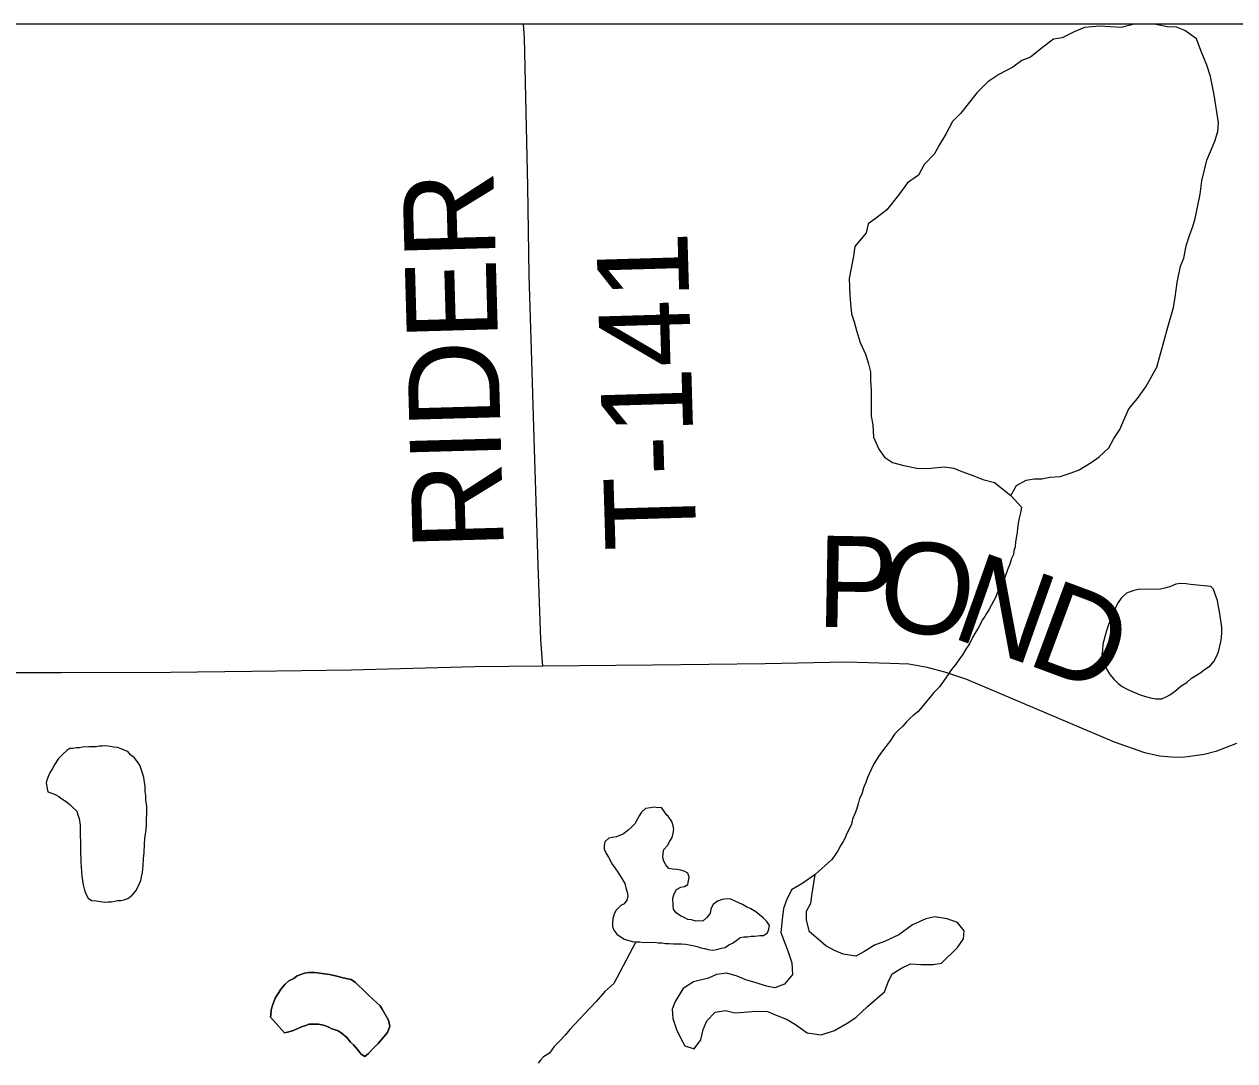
# Model space of a CAD drawing. Extents: x 10.6 to 44.6, y -2.6 to 23.4.
# Drawn here: x 15.419 to 16.174, y 21.68 to 22.327 of the extents above; entities that cross this region are included whole.
import ezdxf

# ---------------------------------------------------------------- set-up
doc = ezdxf.new("R2010")
doc.units = 0
for name, color, linetype in [('GM_X_County', 7, 'Continuous'), ('GM_X_Minor_Lake', 7, 'Continuous'), ('GM_X_Minor_River', 7, 'Continuous'), ('GM_X_Township', 7, 'Continuous'), ('GM_X_Township_Road', 7, 'Continuous'), ('GM_X_Township_Road_Text', 7, 'Continuous')]:
    doc.layers.add(name, color=color, linetype=linetype)

msp = doc.modelspace()

# ---------------------------------------------------------------- linework, layer by layer
at = {"layer": 'GM_X_County'}
msp.add_lwpolyline([(20.00331, 15.53022), (20.00331, 22.32669), (13.20331, 22.32669), (13.20331, 15.52669), (19.84134, 15.52669)], dxfattribs=at)
at = {"layer": 'GM_X_Minor_Lake'}
for points in [[(16.11082, 22.32669), (16.10952, 22.32625), (16.10307, 22.32473), (16.09624, 22.3251), (16.08979, 22.32547), (16.08031, 22.3247), (16.07386, 22.32204), (16.06627, 22.31823), (16.06096, 22.31746), (16.05413, 22.31214), (16.04654, 22.30605), (16.04123, 22.30415), (16.03553, 22.29996), (16.02681, 22.2954), (16.01998, 22.29083), (16.01315, 22.28399), (16.00935, 22.27905), (16.0029, 22.27106), (15.99797, 22.26612), (15.99379, 22.25814), (15.98962, 22.2513), (15.98658, 22.24598), (15.98013, 22.23913), (15.97672, 22.23267), (15.96988, 22.22772), (15.96419, 22.22012), (15.95698, 22.211), (15.95053, 22.20605), (15.94522, 22.20225), (15.94408, 22.19655), (15.93687, 22.18819), (15.93611, 22.18211), (15.93345, 22.16805), (15.93383, 22.1578), (15.93421, 22.15248), (15.93497, 22.14602), (15.93649, 22.14109), (15.938, 22.13577), (15.94028, 22.12818), (15.94369, 22.12097), (15.94559, 22.11489), (15.94672, 22.10995), (15.94672, 22.10464), (15.9471, 22.09856), (15.9471, 22.08223), (15.94824, 22.07691), (15.94862, 22.06932), (15.95203, 22.06172), (15.95544, 22.05679), (15.96038, 22.05338), (15.96758, 22.05149), (15.97555, 22.04998), (15.98238, 22.0496), (15.99263, 22.05076), (15.9987, 22.05), (16.00363, 22.04773), (16.01122, 22.04508), (16.01691, 22.04281), (16.02412, 22.04092), (16.03436, 22.03295)], [(16.05371, 22.04323), (16.05864, 22.04437), (16.06509, 22.04476), (16.07192, 22.04705), (16.07685, 22.04895), (16.08444, 22.05352), (16.08938, 22.05694), (16.09545, 22.06264), (16.09848, 22.06834), (16.10228, 22.07405), (16.10531, 22.08127), (16.10797, 22.08697), (16.11328, 22.09343), (16.1186, 22.10065), (16.12543, 22.11281), (16.13226, 22.13789), (16.13568, 22.15005), (16.13682, 22.1565), (16.13796, 22.16562), (16.14023, 22.17588), (16.14213, 22.18082), (16.14365, 22.18842), (16.14593, 22.19564), (16.14783, 22.20058), (16.14934, 22.20552), (16.15238, 22.22071), (16.15352, 22.22907), (16.15656, 22.24199), (16.15884, 22.24731), (16.16149, 22.25377), (16.16339, 22.25984), (16.16377, 22.26516), (16.16112, 22.28263), (16.15884, 22.29402), (16.15656, 22.30124), (16.15277, 22.31035), (16.15012, 22.31756), (16.14291, 22.32287), (16.1376, 22.32477), (16.13191, 22.32514), (16.12584, 22.32627), (16.12351, 22.32669)], [(16.03436, 22.03295), (16.03777, 22.03903), (16.04384, 22.04246), (16.04878, 22.04322), (16.05371, 22.04323)], [(16.15912, 21.9761), (16.14629, 21.97736), (16.14363, 21.9777), (16.14021, 21.97803), (16.13718, 21.97761), (16.13379, 21.97605), (16.13114, 21.97526), (16.12773, 21.97445), (16.11369, 21.97427), (16.11029, 21.97346), (16.10652, 21.97189), (16.10314, 21.96881), (16.10127, 21.96613), (16.09979, 21.96345), (16.09869, 21.96002), (16.09647, 21.95582), (16.095, 21.95162), (16.0939, 21.94857), (16.09318, 21.94553), (16.09173, 21.94019), (16.09139, 21.93639), (16.09105, 21.93373), (16.09185, 21.93032), (16.09264, 21.92768), (16.0942, 21.92428), (16.09613, 21.92127), (16.09845, 21.91826), (16.10114, 21.91564), (16.10382, 21.91378), (16.10649, 21.9123), (16.10955, 21.91082), (16.11488, 21.90861), (16.11831, 21.90752), (16.12136, 21.9068), (16.12478, 21.90609), (16.12858, 21.90614)], [(16.12858, 21.90614), (16.13122, 21.90731), (16.13386, 21.90886), (16.13724, 21.91118), (16.14062, 21.91426), (16.14401, 21.91621), (16.14701, 21.91891), (16.15229, 21.92201), (16.15567, 21.92471), (16.15868, 21.92665), (16.16093, 21.92934), (16.16241, 21.93202), (16.16389, 21.93545), (16.16533, 21.94154), (16.16568, 21.94421), (16.16601, 21.94763), (16.16598, 21.95066), (16.16556, 21.95369), (16.16432, 21.96165), (16.16353, 21.96468), (16.16311, 21.96733), (16.16193, 21.97073), (16.16075, 21.97451), (16.15912, 21.9761)], [(15.49327, 21.80654), (15.49357, 21.81035), (15.49384, 21.81529), (15.49414, 21.8191), (15.49447, 21.82177), (15.49479, 21.82444), (15.4951, 21.82748), (15.49502, 21.83128), (15.49534, 21.83433), (15.49524, 21.83888), (15.49477, 21.84305), (15.49471, 21.84571), (15.49428, 21.84836), (15.49421, 21.8514), (15.49377, 21.85405), (15.49333, 21.85708), (15.49251, 21.85972), (15.49088, 21.86463), (15.48892, 21.86762), (15.48736, 21.86949), (15.48542, 21.87097), (15.48348, 21.8732), (15.48156, 21.87392), (15.47925, 21.87501), (15.47695, 21.87572), (15.47466, 21.87605), (15.47238, 21.87638), (15.4697, 21.8767), (15.46742, 21.87666), (15.46552, 21.87662), (15.46363, 21.87619), (15.46097, 21.87614), (15.45907, 21.87609), (15.45526, 21.87601), (15.45337, 21.87559), (15.45147, 21.87555), (15.4492, 21.87512), (15.4473, 21.87508), (15.44542, 21.8739), (15.44281, 21.87156), (15.4402, 21.86884), (15.43799, 21.86538), (15.43653, 21.86268), (15.43506, 21.86037), (15.43397, 21.85807), (15.43288, 21.85538), (15.43254, 21.85348), (15.43365, 21.84813)], [(15.43365, 21.84813), (15.43533, 21.84746), (15.43802, 21.84638), (15.44033, 21.84529), (15.44226, 21.84381), (15.44496, 21.84197), (15.44728, 21.84012), (15.44923, 21.83826), (15.45156, 21.83603), (15.45236, 21.83377), (15.45317, 21.83151), (15.45364, 21.82734), (15.45369, 21.82506), (15.45374, 21.82278), (15.4538, 21.82012), (15.45384, 21.81784), (15.4539, 21.81519), (15.45396, 21.81253), (15.45402, 21.80987), (15.45408, 21.80683), (15.45414, 21.80417), (15.45471, 21.79545), (15.45514, 21.79279), (15.45558, 21.79014), (15.45641, 21.78674), (15.45722, 21.78448), (15.4588, 21.78185), (15.46074, 21.78038), (15.46378, 21.78006), (15.46645, 21.77974), (15.46874, 21.77941), (15.47102, 21.77946), (15.47331, 21.77951), (15.4752, 21.77993), (15.47709, 21.78035), (15.47899, 21.78039), (15.48089, 21.78081), (15.48353, 21.78163), (15.48615, 21.78359), (15.48838, 21.7863), (15.48948, 21.78822), (15.49057, 21.79052), (15.49166, 21.79283), (15.49199, 21.79512), (15.4927, 21.79779), (15.49299, 21.80198), (15.49327, 21.80654), (15.49357, 21.81035), (15.49384, 21.81529), (15.49414, 21.8191), (15.49447, 21.82177), (15.49479, 21.82444), (15.4951, 21.82748), (15.49502, 21.83128), (15.49534, 21.83433), (15.49524, 21.83888), (15.49477, 21.84305), (15.49471, 21.84571), (15.49428, 21.84836), (15.49421, 21.8514), (15.49377, 21.85405), (15.49333, 21.85708), (15.49251, 21.85972), (15.49088, 21.86463), (15.48892, 21.86762), (15.48736, 21.86949), (15.48542, 21.87097), (15.48348, 21.8732), (15.48156, 21.87392), (15.47925, 21.87501), (15.47695, 21.87572), (15.47466, 21.87605), (15.47238, 21.87638), (15.4697, 21.8767), (15.46742, 21.87666), (15.46552, 21.87662), (15.46363, 21.87619), (15.46097, 21.87614), (15.45907, 21.87609), (15.45526, 21.87601), (15.45337, 21.87559), (15.45147, 21.87555), (15.4492, 21.87512), (15.4473, 21.87508), (15.44542, 21.8739), (15.44281, 21.87156), (15.4402, 21.86884), (15.43799, 21.86538), (15.43653, 21.86268), (15.43506, 21.86037), (15.43397, 21.85807), (15.43288, 21.85538), (15.43254, 21.85348), (15.43365, 21.84813)], [(15.43365, 21.84813), (15.43533, 21.84746), (15.43802, 21.84638), (15.44033, 21.84529), (15.44226, 21.84381), (15.44496, 21.84197), (15.44728, 21.84012), (15.44923, 21.83826), (15.45156, 21.83603), (15.45236, 21.83377), (15.45317, 21.83151), (15.45364, 21.82734), (15.45369, 21.82506), (15.45374, 21.82278), (15.4538, 21.82012), (15.45384, 21.81784), (15.4539, 21.81519), (15.45396, 21.81253), (15.45402, 21.80987), (15.45408, 21.80683), (15.45414, 21.80417), (15.45471, 21.79545), (15.45514, 21.79279), (15.45558, 21.79014), (15.45641, 21.78674), (15.45722, 21.78448), (15.4588, 21.78185), (15.46074, 21.78038), (15.46378, 21.78006), (15.46645, 21.77974), (15.46874, 21.77941), (15.47102, 21.77946), (15.47331, 21.77951), (15.4752, 21.77993), (15.47709, 21.78035), (15.47899, 21.78039), (15.48089, 21.78081), (15.48353, 21.78163), (15.48615, 21.78359), (15.48838, 21.7863), (15.48948, 21.78822), (15.49057, 21.79052), (15.49166, 21.79283), (15.49199, 21.79512), (15.4927, 21.79779), (15.49299, 21.80198), (15.49327, 21.80654)], [(15.81979, 21.83352), (15.81634, 21.83823), (15.81406, 21.8382), (15.81178, 21.83855), (15.80951, 21.83814), (15.80648, 21.83772), (15.80385, 21.83541), (15.80236, 21.83311), (15.80125, 21.83082), (15.79977, 21.82814), (15.79752, 21.82584), (15.79526, 21.82391), (15.79263, 21.82197), (15.79037, 21.82081), (15.7881, 21.82002), (15.78583, 21.81961), (15.78356, 21.8192), (15.78093, 21.81688), (15.78058, 21.8146), (15.78061, 21.81232), (15.78178, 21.80968), (15.78332, 21.80743), (15.78566, 21.8029), (15.7872, 21.80064), (15.78913, 21.79801), (15.79068, 21.79576), (15.79223, 21.79312), (15.79339, 21.79086), (15.79419, 21.78821), (15.79498, 21.78556), (15.79538, 21.78329), (15.79466, 21.78062), (15.79317, 21.77833), (15.79091, 21.77716), (15.78791, 21.77408), (15.7868, 21.77179), (15.78607, 21.76912), (15.78573, 21.76646)], [(15.88257, 21.76015), (15.8833, 21.76244), (15.88366, 21.76472), (15.8821, 21.76735), (15.8798, 21.7696), (15.8752, 21.77334), (15.87214, 21.7752), (15.86947, 21.7763), (15.8668, 21.77778), (15.86451, 21.77889), (15.86222, 21.78), (15.85955, 21.7811), (15.85727, 21.78145), (15.85423, 21.78103), (15.85121, 21.77985), (15.84858, 21.77792), (15.84709, 21.77524), (15.84675, 21.7722), (15.84451, 21.76952), (15.84226, 21.76759), (15.8377, 21.76753), (15.83504, 21.76825), (15.83276, 21.7686), (15.83046, 21.76971), (15.82817, 21.77082), (15.8255, 21.77268), (15.82395, 21.77494), (15.82354, 21.77721), (15.82349, 21.78177), (15.82421, 21.78443), (15.8257, 21.78711), (15.82833, 21.78866), (15.83061, 21.78907), (15.83287, 21.79024), (15.83357, 21.7948), (15.83278, 21.79745), (15.83049, 21.79856), (15.8282, 21.79929), (15.82592, 21.79964), (15.82326, 21.79998), (15.82098, 21.80033), (15.81905, 21.80258), (15.81789, 21.80485), (15.8171, 21.80711), (15.81745, 21.80978), (15.8178, 21.81206), (15.82004, 21.81474), (15.82153, 21.81742), (15.82302, 21.81972), (15.82374, 21.82238), (15.82409, 21.82467), (15.82369, 21.82694), (15.8229, 21.82959), (15.82058, 21.83297), (15.81979, 21.83352)], [(15.91216, 21.79657), (15.90457, 21.79124), (15.89736, 21.78706), (15.89432, 21.7806), (15.89242, 21.77528), (15.89166, 21.76844), (15.8909, 21.76046), (15.89545, 21.74831), (15.89773, 21.74148), (15.89811, 21.73426), (15.89317, 21.72818), (15.8871, 21.7259), (15.88179, 21.72703), (15.87534, 21.72892), (15.86889, 21.73081), (15.86358, 21.73309), (15.85713, 21.73498), (15.85068, 21.73421), (15.84575, 21.73193), (15.83626, 21.72964), (15.82981, 21.72545), (15.82488, 21.71747), (15.82298, 21.71253), (15.82336, 21.70683), (15.82563, 21.7), (15.82829, 21.69468), (15.83095, 21.68975), (15.83664, 21.68786), (15.84081, 21.69356), (15.84233, 21.70002), (15.84461, 21.70534), (15.84992, 21.71066), (15.85637, 21.71181), (15.86206, 21.7103), (15.86775, 21.71068), (15.87534, 21.71145), (15.88255, 21.71108), (15.889, 21.70843), (15.89469, 21.70616)], [(15.91216, 21.79657), (15.90457, 21.79124), (15.89736, 21.78706), (15.89432, 21.7806), (15.89242, 21.77528), (15.89166, 21.76844), (15.8909, 21.76046), (15.89545, 21.74831), (15.89773, 21.74148), (15.89811, 21.73426), (15.89317, 21.72818), (15.8871, 21.7259), (15.88179, 21.72703), (15.87534, 21.72892), (15.86889, 21.73081), (15.86358, 21.73309), (15.85713, 21.73498), (15.85068, 21.73421), (15.84575, 21.73193), (15.83626, 21.72964), (15.82981, 21.72545), (15.82488, 21.71747), (15.82298, 21.71253), (15.82336, 21.70683), (15.82563, 21.7), (15.82829, 21.69468), (15.83095, 21.68975), (15.83664, 21.68786), (15.84081, 21.69356), (15.84233, 21.70002), (15.84461, 21.70534), (15.84992, 21.71066), (15.85637, 21.71181), (15.86206, 21.7103), (15.86775, 21.71068), (15.87534, 21.71145), (15.88255, 21.71108), (15.889, 21.70843), (15.89469, 21.70616), (15.9, 21.70312), (15.90721, 21.69781), (15.91594, 21.69668), (15.92428, 21.69935), (15.93225, 21.70392), (15.93756, 21.70734), (15.94477, 21.71419), (15.9554, 21.72331), (15.95768, 21.72939), (15.96033, 21.73472), (15.96602, 21.73814), (15.97172, 21.74081), (15.97817, 21.74043), (15.98575, 21.74044), (15.99107, 21.74121), (16.00093, 21.75109), (16.00473, 21.75641), (16.00511, 21.76135), (16.00093, 21.76667), (15.99448, 21.76894), (15.9869, 21.77007), (15.9812, 21.76892), (15.97286, 21.76512), (15.96451, 21.75903), (15.9554, 21.75484), (15.94933, 21.75256), (15.9425, 21.74837), (15.93757, 21.7457), (15.9296, 21.74683), (15.92429, 21.74911), (15.91898, 21.75214), (15.91405, 21.75631), (15.90874, 21.76086), (15.90684, 21.76808), (15.90684, 21.77378), (15.9095, 21.77872), (15.91026, 21.78479), (15.91216, 21.79657)], [(15.89469, 21.70616), (15.9, 21.70312), (15.90721, 21.69781), (15.91594, 21.69668), (15.92428, 21.69935), (15.93225, 21.70392), (15.93756, 21.70734), (15.94477, 21.71419), (15.9554, 21.72331), (15.95768, 21.72939), (15.96033, 21.73472), (15.96602, 21.73814), (15.97172, 21.74081), (15.97817, 21.74043), (15.98575, 21.74044), (15.99107, 21.74121), (16.00093, 21.75109), (16.00473, 21.75641), (16.00511, 21.76135), (16.00093, 21.76667), (15.99448, 21.76894), (15.9869, 21.77007), (15.9812, 21.76892), (15.97286, 21.76512), (15.96451, 21.75903), (15.9554, 21.75484), (15.94933, 21.75256), (15.9425, 21.74837), (15.93757, 21.7457), (15.9296, 21.74683), (15.92429, 21.74911), (15.91898, 21.75214), (15.91405, 21.75631), (15.90874, 21.76086), (15.90684, 21.76808), (15.90684, 21.77378), (15.9095, 21.77872), (15.91026, 21.78479), (15.91216, 21.79657)], [(15.78573, 21.76646), (15.78575, 21.76418), (15.78654, 21.76191), (15.78847, 21.75928), (15.79306, 21.75631), (15.79535, 21.75558), (15.79801, 21.75485), (15.80029, 21.7545), (15.80295, 21.75454), (15.80523, 21.75419), (15.81206, 21.75428), (15.81434, 21.75393), (15.81662, 21.75396), (15.8189, 21.75361), (15.82118, 21.75364), (15.82384, 21.7533), (15.82877, 21.75336), (15.83143, 21.75302), (15.83371, 21.75267), (15.83599, 21.75232), (15.83866, 21.75159), (15.84094, 21.75087), (15.84323, 21.75052), (15.84551, 21.74979), (15.84817, 21.74944), (15.85082, 21.74986), (15.85385, 21.75066), (15.85612, 21.75107), (15.85838, 21.75262), (15.86064, 21.75378), (15.86327, 21.75572), (15.86553, 21.75727), (15.8678, 21.75767), (15.87008, 21.75771), (15.87235, 21.75811), (15.87463, 21.75815), (15.87766, 21.75856), (15.87993, 21.7586), (15.88257, 21.76015)], [(15.64212, 21.71251), (15.64093, 21.71476), (15.63899, 21.71624), (15.63627, 21.71884), (15.63317, 21.72181), (15.63006, 21.72478), (15.62734, 21.72738), (15.6254, 21.72924), (15.6227, 21.73108), (15.62079, 21.73142), (15.61773, 21.73212), (15.61391, 21.73317), (15.60932, 21.73421), (15.60474, 21.73487), (15.60016, 21.73553), (15.59636, 21.73545), (15.5937, 21.73501), (15.59144, 21.7342), (15.58917, 21.73339), (15.58693, 21.73182), (15.58392, 21.73024), (15.5813, 21.7279), (15.57908, 21.7252), (15.57687, 21.72173), (15.5754, 21.71941), (15.57396, 21.71558), (15.57289, 21.71214), (15.57258, 21.70909), (15.5724, 21.70763)], [(15.5724, 21.70763), (15.57258, 21.70909), (15.57289, 21.71214), (15.57396, 21.71558), (15.5754, 21.71941), (15.57687, 21.72173), (15.57908, 21.7252), (15.5813, 21.7279), (15.58392, 21.73024), (15.58693, 21.73182), (15.58917, 21.73339), (15.59144, 21.7342), (15.5937, 21.73501), (15.59636, 21.73545), (15.60016, 21.73553), (15.60474, 21.73487), (15.60932, 21.73421), (15.61391, 21.73317), (15.61773, 21.73212), (15.62079, 21.73142), (15.6227, 21.73108), (15.6254, 21.72924), (15.62734, 21.72738), (15.63006, 21.72478), (15.63317, 21.72181), (15.63627, 21.71884), (15.63899, 21.71624), (15.64093, 21.71476), (15.64212, 21.71251), (15.64607, 21.70575), (15.64691, 21.70197), (15.64547, 21.69814), (15.64324, 21.69543), (15.63953, 21.69117), (15.63655, 21.68807), (15.63358, 21.68496), (15.63134, 21.68302), (15.62902, 21.68449), (15.62668, 21.68747), (15.62433, 21.69046), (15.6224, 21.69194), (15.62005, 21.69493), (15.61656, 21.69789), (15.61464, 21.69899), (15.61272, 21.69971), (15.6108, 21.70043), (15.6085, 21.70152), (15.60543, 21.70259), (15.60237, 21.70328), (15.59857, 21.7032), (15.59629, 21.70315), (15.5944, 21.70235), (15.59176, 21.70153), (15.58912, 21.70034), (15.5861, 21.69913), (15.58308, 21.6983), (15.58119, 21.69788), (15.5724, 21.70763)], [(15.5724, 21.70763), (15.58119, 21.69788), (15.58308, 21.6983), (15.5861, 21.69913), (15.58912, 21.70034), (15.59176, 21.70153), (15.5944, 21.70235), (15.59629, 21.70315), (15.59857, 21.7032), (15.60237, 21.70328), (15.60543, 21.70259), (15.6085, 21.70152), (15.6108, 21.70043), (15.61272, 21.69971), (15.61464, 21.69899), (15.61656, 21.69789), (15.62005, 21.69493), (15.6224, 21.69194), (15.62433, 21.69046), (15.62668, 21.68747), (15.62902, 21.68449), (15.63134, 21.68302), (15.63358, 21.68496), (15.63655, 21.68807), (15.63953, 21.69117), (15.64324, 21.69543), (15.64547, 21.69814), (15.64691, 21.70197), (15.64607, 21.70575), (15.64212, 21.71251)]]:
    msp.add_lwpolyline(points, dxfattribs=at)
at = {"layer": 'GM_X_Minor_River'}
for points in [[(16.03436, 22.03295), (16.04093, 22.02553), (16.04024, 22.02209), (16.03955, 22.01866), (16.03886, 22.01561), (16.03854, 22.01256), (16.03822, 22.00989), (16.03789, 22.00761), (16.03721, 22.00379), (16.03689, 22.00075), (16.03618, 21.99845), (16.03585, 21.99616), (16.03476, 21.99348), (16.0337, 21.99004), (16.03225, 21.98659), (16.03082, 21.98238), (16.029, 21.97854), (16.02717, 21.97508), (16.02571, 21.97201), (16.02463, 21.96932), (16.02354, 21.96702), (16.02208, 21.96433), (16.02061, 21.96163), (16.01914, 21.95932), (16.01804, 21.9574), (16.01656, 21.95547), (16.0151, 21.9524), (16.01401, 21.95009), (16.01254, 21.94778), (16.01033, 21.94431), (16.00851, 21.94047), (16.0063, 21.93701), (16.00409, 21.93354), (16.00188, 21.93045), (16.00003, 21.92775), (15.99818, 21.92543), (15.9967, 21.9235), (15.99523, 21.92119), (15.98969, 21.91347), (15.98634, 21.90998), (15.98374, 21.90688), (15.98152, 21.90417), (15.97892, 21.90107), (15.97632, 21.89798), (15.97333, 21.89563), (15.97146, 21.89407), (15.96923, 21.89175), (15.96701, 21.88904), (15.96439, 21.8867), (15.96179, 21.88398), (15.95921, 21.88013), (15.95625, 21.87626), (15.95366, 21.87279), (15.95181, 21.87009), (15.95034, 21.86778), (15.94887, 21.86546), (15.94741, 21.86239), (15.94596, 21.85932), (15.94487, 21.85702), (15.94379, 21.85395), (15.94234, 21.8505), (15.94129, 21.84668), (15.93982, 21.84399), (15.93913, 21.84056), (15.93806, 21.83711), (15.93698, 21.83443), (15.93553, 21.83098), (15.93484, 21.82792), (15.93338, 21.82485), (15.93192, 21.82216), (15.93084, 21.81948), (15.92974, 21.81717), (15.92827, 21.81486), (15.92644, 21.8114), (15.92386, 21.80755), (15.92238, 21.80561), (15.91216, 21.79657)], [(15.80029, 21.7545), (15.78671, 21.72857), (15.78111, 21.72351), (15.7785, 21.72079), (15.77554, 21.71731), (15.77181, 21.71343), (15.76215, 21.70296), (15.75917, 21.69985), (15.7562, 21.69637), (15.75286, 21.69288), (15.74951, 21.68938), (15.74655, 21.68514), (15.7428, 21.68278), (15.74094, 21.68084), (15.73946, 21.67891)]]:
    msp.add_lwpolyline(points, dxfattribs=at)
at = {"layer": 'GM_X_Township'}
msp.add_line((19.97013, 22.32669), (15.23634, 22.32669), dxfattribs=at)
at = {"layer": 'GM_X_Township_Road'}
for points in [[(15.74229, 21.92644), (15.74107, 21.94292), (15.73938, 21.98971), (15.73695, 22.0685), (15.7355, 22.11674), (15.7338, 22.17032), (15.73307, 22.22559), (15.73089, 22.3182), (15.73026, 22.32669)], [(16.17502, 21.8782), (16.16217, 21.87335), (16.1549, 21.87141), (16.14762, 21.87044), (16.14108, 21.86947), (16.13453, 21.86971), (16.12702, 21.87044), (16.1178, 21.87238), (16.09889, 21.87916), (16.00677, 21.9182), (15.9932, 21.9228), (15.98205, 21.92571), (15.97065, 21.92765), (15.95877, 21.92813), (15.93186, 21.92886), (15.88095, 21.92789), (15.81065, 21.92717), (15.74229, 21.92644), (15.69986, 21.92595), (15.62277, 21.92401), (15.56071, 21.92304), (15.51004, 21.92256), (15.44216, 21.92232), (15.38713, 21.92232)]]:
    msp.add_lwpolyline(points, dxfattribs=at)

# ---------------------------------------------------------------- texts
at = {"layer": 'GM_X_Township_Road_Text'}
for s, height, rotation, p in [('RIDER', 0.056818, 91.60329, (15.71804, 21.99949)), ('T-141', 0.056818, 91.67044, (15.83823, 21.99953)), ('P', 0.05682, 358.99266, (15.91274, 21.95108)), ('O', 0.05682, 352.58807, (15.94939, 21.95053)), ('N', 0.05682, 340.466, (15.99589, 21.94482)), ('D', 0.05682, 339.60981, (16.0428, 21.92817))]:
    msp.add_text(s, height=height, rotation=rotation, dxfattribs=at).set_placement(p)

doc.saveas('drawing.dxf')
